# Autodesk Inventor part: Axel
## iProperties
Author: Tobben
Created: 2001-12
Part Number: Axel
Material: SS2172
Document SubType Name: Modeling
Designer: Tobben
Control State: 0
Master: False
Checked Out: False
PropertySet Name: Design Tracking Control
Shininess: 64.0
Angle Display Precision: 2
Document Length Units: 11269
Document Angle Units: 11283
Document Time Units: 11279
Document Mass Units: 11290
Document Length Units Precision: 3
Document Angle Units Precision: 2
Compacted: False
PropertySet Name: _Private Model Information
Density: 0.0
Volumn: 0.0
Area: 0.0
PropertySet Name: Model Information
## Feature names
1. Extrusion1
